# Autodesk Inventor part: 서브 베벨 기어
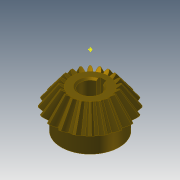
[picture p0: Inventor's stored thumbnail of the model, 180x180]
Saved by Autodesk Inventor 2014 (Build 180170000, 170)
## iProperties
Created: 2014-10
Part Number: 서브 베벨 기어
Material: 강철
Document SubType Name: Modeling
Designer: KYOUNG IL JANG
Categories: <?xml version="1.0" encoding="UTF-16"?> <MemberInstance><Categories><FamilyTemplate><FamilyTemplateParameter ValueType="xs:double" Id="1" ObjectReferenceKey="da
Mass: 134.694 g
Surface Area: 63.6518 cm^2
Volume: 17.1585 cm^3
Density: 7.85 g/cm^3
Appearance: Brindle
CustomPartVersion: 1
Company: 한국ATC센터
Author: KYOUNG IL JANG
Revision Number: 1
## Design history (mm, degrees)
node "맨 위 점"
node "메쉬 평면2"
sketch "톱니 본체 스케치"
  geometry: L1 (0, 0)-(18.003, -31.331); L2 (18.003, -31.331)-(21.664, -28.891); L3 (21.664, -28.891)-(0, 0); L4 (20, -30)-(0, 0); L5 (10.813, -18.818)-(13.012, -17.352); L6 (18.003, -31.331)-(10.813, -18.818); L7 (21.664, -28.891)-(13.012, -17.352); L8 (0, -39.387)-(0, 6.564) reference; L9 (0, -30)-(21.664, -30)
  constraints: 16 end point, 4 point on line, 3 perpendicular, 2 collinear, 1 horizontal alignment, 1 vertical alignment
  dimensions: "d0" = 40 diameter of L4.start L8 (= da_de); "d1" = 36.00616 diameter of L1.end L8 (= da_dfe); "d2" = 43.3282 diameter of L2.end L8 (= da_dae); "d3" = 14.4 distance between parallel lines of L2 L5 (= da_b); "d4" = 28.8906 vertical distance of L2.end L1.start (= da_ve)
revolve "톱니 본체" sketch "톱니 본체 스케치" stored, may be unused: angle "d5" = 90 deg
node "시작점"
node "톱니 평면"
sketch "시작 스케치"
  geometry: L1 (0, -23.505)-(0, 10.645) reference; L2 (-0.834, -2.928)-(0.834, -2.928); A1 r 8.898 centre (-9.698, -3.713) between (-0.834, -2.928) and (-3.903, 3.04); A2 r 8.898 centre (9.698, -3.713) between (3.903, 3.04) and (0.834, -2.928); A3 r 27.357 centre (0, -24.037) between (3.903, 3.04) and (-3.903, 3.04); 1 further point
  constraints: 6 point on circle, 3 centre point, 3 symmetric about line, 2 end point, 1 coincident, 1 perpendicular, 1 other
  dimensions: "d7" = 8.89846 radius of A1 (= fd_rr); "d8" = 9.69794 horizontal distance of point (0, -24.037) A1.centre (= fd_x); "d9" = 20.32439 vertical distance of point (0, -24.037) A1.centre (= fd_y); "d57" = 27.35701 radius of A3 (= 0.5 x fd_dva + 0.3 x da_he); "d58" = 21.10901 distance from line of A3.centre L2 (= 0.5 x fd_dva - 1.12 x da_he)
node "끝점"
  node "끝 평면"
sketch "3D 스케치 오른쪽"
  node "Helical Curve Right" dims "d65" = 229.90621 (computed from da_dm, da_delta, da_beta), "d66" = 31.5, "d67" = 40 (= da_de), "d68" = -5.88003 (= -da_delta), "d69" = 12.16458 (computed from fd_loft, da_delta)
node "끝 평면 오른쪽"
sketch "끝 스케치 오른쪽"
  geometry: L1 (0, -22.649)-(0, 12.15) reference; L2 (-0.497, -1.72)-(0.497, -1.72); A1 r 5.299 centre (-5.775, -2.187) between (-0.497, -1.72) and (-2.324, 1.834); A2 r 5.299 centre (5.775, -2.187) between (2.324, 1.834) and (0.497, -1.72); A3 r 16.291 centre (0, -14.29) between (2.324, 1.834) and (-2.324, 1.834); 1 further point
  constraints: 6 point on circle, 3 centre point, 3 symmetric about line, 2 end point, 1 coincident, 1 perpendicular, 1 other
  dimensions: "d70" = 5.77526 horizontal distance of A3.centre A1.centre (computed from fd_x, fd_ratio); "d71" = 12.10346 vertical distance of point (0, -14.29) A1.centre (computed from fd_y, fd_ratio); "d72" = 5.29916 radius of A1 (computed from fd_rr, fd_ratio); "d73" = 12.57071 distance from line of point (0, -14.29) L2 (computed from d58, fd_ratio); "d74" = 16.29149 radius of A3 (computed from d57, fd_ratio)
feature "로프트 오른쪽" sketch "끝 스케치 오른쪽" dims "d75" = 0, "d77" = 0, "d79" = 0, "d80" = 90 deg, "d85" = 20, "d92" = 90 deg, "d93" = 90 deg, "da_teethtype" = 0 [user parameter]
sketch "3D 스케치 왼쪽"
  node "Helical Curve Left" dims "d26" = 229.90621 (computed from da_dm, da_delta, da_beta), "d27" = 12.16458 (computed from fd_loft, da_delta), "d28" = 40 (= da_de), "d29" = -5.88003 (= -da_delta)
node "끝 평면 왼쪽"
sketch "끝 스케치 왼쪽" dims "d56" = 10.82768 (derived)
  geometry: L1 (0, -35.087)-(0, 18.089) reference; L2 (-0.497, -1.716)-(0.497, -1.716); A1 r 5.299 centre (-5.775, -2.183) between (-0.497, -1.716) and (-2.324, 1.838); A2 r 5.299 centre (5.775, -2.183) between (2.324, 1.838) and (0.497, -1.716); A3 r 16.291 centre (0, -14.287) between (2.324, 1.838) and (-2.324, 1.838); 2 further points; 1 other entity
  constraints: 6 point on circle, 3 centre point, 3 symmetric about line, 2 end point, 1 coincident, 2 other
  dimensions: "d30" = 5.29916 radius of A1 (computed from fd_rr, fd_ratio); "d31" = 5.77526 horizontal distance of point (0, -14.287) A1.centre (computed from fd_x, fd_ratio); "d32" = 12.10346 vertical distance of A1.centre point (0, -14.287) (computed from fd_y, fd_ratio); "d61" = 16.29149 radius of A3 (computed from d57, fd_ratio); "d62" = 12.57071 distance from line of point (0, -14.287) L2 (computed from d58, fd_ratio)
feature "로프트 왼쪽" sketch "끝 스케치 왼쪽" dims "d35" = 0, "d37" = 0, "d39" = 0, "d40" = 90 deg, "d84" = 10, "d90" = 90 deg, "d91" = 90 deg, "da_teethtype" = 0 [user parameter]
sketch "본체 스케치"
  geometry: L1 (0, -35.038)-(0, -19.531) reference; L2 (18.003, -31.331)-(10.813, -18.818) reference; L3 (10.813, -18.818)-(0, -18.818); L4 (18.003, -31.331)-(0, -31.331)
  constraints: 4 end point, 2 perpendicular, 2 point on line
revolve "본체 고정" sketch "본체 스케치" stored, may be unused: angle "d46" = 90 deg
feature "피치 지름" dims angle "d47" = 90 deg
sketch "스케치8"
  geometry: C1 r 17 at (0, 0); 1 further point
  constraints: 1 centre point, 1 coincident
  dimensions: "d94" = 34 diameter of C1
extrude "돌출1" join sketch "스케치8" distance "d95" = 10; taper "d96" = 0 deg
sketch "스케치9"
  geometry: 1 further point
hole "구멍1" sketch "스케치9" at (0, 0) diameter "d97" = 12; stored, may be unused: countersink angle "d101" = 90 deg, drill point angle "d103" = 118 deg; dims "d98" = 6, "d99" = 4, "d100" = 2, "d102" = 8
sketch "스케치10"
  geometry: 1 further point
sketch "스케치11"
  geometry: 1 further point
sketch "스케치12"
  geometry: L1 (-2, 5.657)-(-2, 7.8); L2 (-2, 7.8)-(2, 7.8); L3 (2, 7.8)-(2, 5.657); A1 r 6 centre (0, 0) between (-2, 5.657) and (2, 5.657) reference; 1 further point
  constraints: 6 end point, 2 parallel, 2 point on circle, 1 perpendicular, 1 vertical
  dimensions: "d104" = 4 distance of L1.end L2.end; "d105" = 13.8 dimension on A1 L2
extrude "돌출2" cut sketch "스케치12" stored distance "d106" = 7; taper "d107" = 0 deg
chamfer "모따기1" distance "d108" = 1; stored, may be unused: second distance "d109" = 2, angle "d110" = 45 deg
body "Solid1"
feature "로프트" dims "d17" = 0, "d18" = 90 deg, "d19" = 0, "d20" = 90 deg, "d89" = 0, "da_teethtype" = 0 [user parameter]
pattern_circular "원형 패턴" dims angle "d22" = 360 deg, "d88" = 0, "da_teethtype" = 0 [user parameter]
pattern_circular "원형 패턴 오른쪽" dims angle "d82" = 360 deg, "da_teethtype" = 0 [user parameter]
pattern_circular "원형 패턴 왼쪽" dims angle "d42" = 360 deg, "da_teethtype" = 0 [user parameter]
sketch "끝 스케치"
  geometry: L1 (0, -15.359)-(0, 6.983) reference; L2 (-0.497, -1.72)-(0.497, -1.72); A1 r 5.299 centre (-5.775, -2.187) between (-0.497, -1.72) and (-2.324, 1.834); A2 r 5.299 centre (5.775, -2.187) between (2.324, 1.834) and (0.497, -1.72); A3 r 16.291 centre (0, -14.29) between (2.324, 1.834) and (-2.324, 1.834); 1 further point
  constraints: 6 point on circle, 3 centre point, 3 symmetric about line, 2 end point, 1 coincident, 1 other
  dimensions: "d12" = 5.29916 radius of A1 (computed from fd_rr, fd_ratio); "d15" = 5.77526 horizontal distance of A1.centre point (0, -14.29) (computed from fd_x, fd_ratio); "d16" = 12.10346 vertical distance of A1.centre point (0, -14.29) (computed from fd_y, fd_ratio); "d59" = 16.29149 radius of A3 (computed from d57, fd_ratio); "d60" = 12.57071 distance from line of A3.centre L2 (computed from d58, fd_ratio)
sketch "Sketch6"
  geometry: L1 (20, -30)-(0, 0) reference; L2 (0, -37.8)-(0, 6.3) reference
body "Srf1"
other parameters: "da_b" = 14.4 [user parameter; used in 2 equation terms], "da_de" = 40 [user parameter; used in 4 equation terms], "da_dae" = 43.3282 [user parameter; used in 2 equation terms], "da_dfe" = 36.00616 [user parameter; used in 1 equation term], "da_le" = 36.05551 [user parameter; used in 1 equation term], "da_omega" = 90 deg [user parameter; used in 1 equation term], "da_beta" = 0 [user parameter; used in 2 equation terms], "da_delta" = 5.88003 [user parameter; used in 8 equation terms], "da_alpha" = 20 deg [user parameter; used in 2 equation terms], "da_he" = 4.4 [user parameter; used in 4 equation terms], "da_ve" = 28.8906 [user parameter; used in 1 equation term], "fd_dv" = 48.07402 (computed from da_de, da_delta) [user parameter; used in 1 equation term], "fd_dva" = 52.07402 (computed from da_dae, da_delta) [user parameter; used in 3 equation terms], "fd_dvb" = 45.1748 (computed from fd_dv, da_alpha) [user parameter; used in 2 equation terms], "da_zv" = 240.37008 [user parameter; used in 1 equation term], "fd_loft" = 14.62 (= da_b + 0.05 x da_he) [user parameter; used in 4 equation terms], "fd_ratio" = 5.95514 (computed from da_le, fd_loft) [user parameter; used in 15 equation terms], "fd_rr" = 8.89846 (computed from fd_dd, fd_dvb) [user parameter; used in 6 equation terms], "fd_angle" = 0.66075 (computed from da_zv) [user parameter; used in 4 equation terms], "fd_x1" = 1.58709 (computed from da_dvw, fd_angle) [user parameter; used in 1 equation term], "fd_y1" = 23.98456 (computed from da_dvw, fd_angle) [user parameter; used in 1 equation term], "fd_x2" = 8.11084 (computed from fd_rr, fd_angle2, fd_angle) [user parameter; used in 1 equation term], "fd_y2" = 3.66016 (computed from fd_rr, fd_angle2, fd_angle) [user parameter; used in 1 equation term], "fd_x" = 9.69794 (= fd_x1 + fd_x2) [user parameter; used in 4 equation terms], "fd_y" = 20.32439 (= fd_y1 - fd_y2) [user parameter; used in 4 equation terms], "fd_angle2" = 3.57832 (computed from fd_dvb, fd_dd, da_alpha) [user parameter; used in 2 equation terms], "fd_dd" = 48.55402 (= fd_dva - 0.8 x da_he) [user parameter; used in 2 equation terms], "da_dvw" = 48.07402 [user parameter; used in 2 equation terms], "d11" = 14.62 (= fd_loft), "da_dm" = 32.01232 [user parameter; used in 2 equation terms], "da_x" = 0 [user parameter], "da_m" = 2 [user parameter], "d48" = 0, "d49" = 0, "d50" = 90 deg (= da_omega), "d51" = 9 deg (computed from da_z), "d52" = 0, "d53" = 0, "d54" = 0
